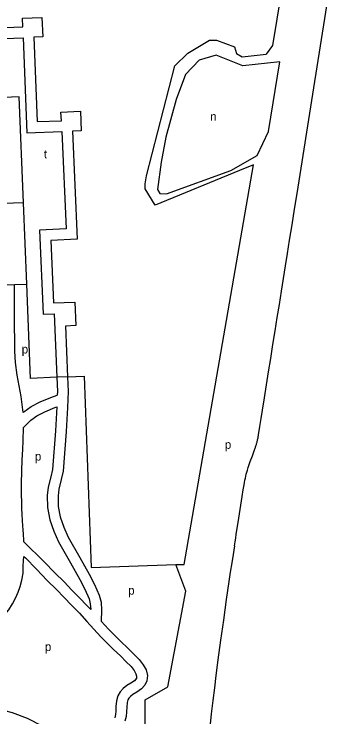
# Model space of a CAD drawing. Extents: x 158358 to 160383, y 379531 to 380764.
# Drawn here: x 160127.9 to 160276, y 379779.7 to 380106.3 of the extents above; entities that cross this region are included whole.
import ezdxf

# ---------------------------------------------------------------- set-up
doc = ezdxf.new("R2010")
doc.units = 0
for name, color, linetype in [('BLT_Basislijn', 7, 'Continuous'), ('BLT_Centroide', 7, 'Continuous'), ('BLT_Vlakafsluiter', 7, 'Continuous')]:
    doc.layers.add(name, color=color, linetype=linetype)

msp = doc.modelspace()

# ---------------------------------------------------------------- linework, layer by layer
at = {"layer": 'BLT_Basislijn'}
for p, q in [((160267.15, 380072.02), (160276.04, 380127.72)), ((160123.03, 379980.48), (160128.03, 379980.66)), ((160128.03, 379980.66), (160133.74, 379980.87))]:
    msp.add_line(p, q, dxfattribs=at)
for points in [[(160273.02, 380260.23), (160275.56, 380259.4), (160247.94, 380091.73)], [(160131.93, 380100.35), (160131.75, 380104.39), (160140.8, 380104.78), (160141.19, 380095.73), (160137.12, 380095.56)], [(160057.38, 380090.08), (160057.1, 380097.61), (160131.93, 380100.35)], [(160137.12, 380095.56), (160138.56, 380056.34), (160149.85, 380056.75)], [(160062.37, 380090.22), (160062.28, 380092.8), (160132.13, 380095.36), (160133.74, 380051.16), (160150.07, 380051.76), (160152.03, 380006.5), (160139.74, 380005.97), (160141.44, 379966.87), (160146.5, 379967.09), (160147.78, 379937.54)], [(160232.68, 380033.58), (160193.4, 380017.54), (160188.82, 380025.11), (160188.85, 380027.46), (160189.4, 380031.21), (160202.52, 380082.29), (160208.59, 380088.18), (160218.69, 380094.16), (160221.96, 380094.16), (160230.35, 380091.15), (160231.21, 380088.08), (160233.92, 380086.4), (160245.05, 380087.77)], [(160132.24, 380018.58), (160130.27, 380067.86), (160115.88, 380067.29), (160114.9, 380091.78), (160062.37, 380090.22)], [(160247.94, 380091.73), (160245.05, 380087.77)], [(160251.38, 380084.09), (160234.24, 380082.31), (160221.71, 380087.21), (160213.85, 380084.97), (160207.47, 380078.19), (160203.18, 380066.58), (160198.36, 380049.08), (160196.22, 380037.47), (160194.48, 380024.75), (160195.64, 380022.96), (160198.67, 380022.78), (160228.67, 380033.7), (160240.83, 380040.67), (160246.02, 380051.71), (160251.38, 380084.09)], [(160259.34, 380022.99), (160267.15, 380072.02)], [(160149.85, 380056.75), (160149.68, 380060.79), (160158.73, 380061.18), (160159.12, 380052.13), (160155.06, 380051.96)], [(160155.06, 380051.96), (160157.24, 380001.73), (160144.95, 380001.19), (160146.21, 379972.08)], [(160203.1, 379850.58), (160206.94, 379850.5), (160239.2, 380036.24), (160232.68, 380033.58)], [(160241.51, 379910.86), (160242.11, 379914.66), (160242.72, 379918.47), (160243.32, 379922.27), (160244.23, 379927.95), (160245.2, 379934.01), (160246.16, 379940.06), (160247.16, 379946.34), (160248.17, 379952.74), (160249.18, 379959.13), (160250.17, 379965.36), (160251.15, 379971.44), (160252.13, 379977.52), (160253.08, 379983.51), (160254.01, 379989.33), (160254.93, 379995.15), (160255.89, 380001.21), (160257.04, 380008.47), (160258.19, 380015.73), (160259.34, 380022.99)], [(160132.24, 380018.58), (160122.99, 380018.24)], [(160133.74, 379980.87), (160132.24, 380018.58)], [(160132.1, 379921.15), (160131.17, 379928.71), (160129.28, 379938.53), (160128.53, 379944.36), (160128.21, 379949.75), (160128.11, 379966.3), (160128.03, 379980.66)], [(160147.78, 379937.54), (160135.49, 379937.05), (160133.74, 379980.87)], [(160146.21, 379972.08), (160156.11, 379972.51), (160156.58, 379961.6), (160151.75, 379961.39)], [(160151.75, 379961.39), (160152.77, 379937.74)], [(160147.78, 379937.54), (160148.06, 379930.96)], [(160152.77, 379937.74), (160160.43, 379938.05), (160163.63, 379849.1), (160203.1, 379850.58)], [(160152.77, 379937.74), (160153.07, 379930.94)], [(160132.1, 379921.15), (160132.39, 379921.45), (160135.84, 379923.95), (160140.06, 379926.1), (160145.03, 379928.23), (160147.97, 379929.26)], [(160148.06, 379930.96), (160147.97, 379929.26)], [(160153.07, 379930.94), (160152.68, 379923.52), (160152.11, 379912.39), (160150.75, 379893.88), (160149.76, 379890.04), (160148.61, 379885.59), (160148.29, 379882.45), (160148.41, 379877.49), (160149.27, 379872.65), (160150.95, 379867.95), (160153.05, 379863.3), (160158.38, 379853.83), (160162.75, 379846.05), (160165.3, 379841.27), (160167.49, 379836.3), (160168.27, 379833.09), (160168.54, 379829.31), (160168.27, 379824.17)], [(160132.33, 379914.24), (160135.67, 379917.65), (160138.46, 379919.67), (160142.19, 379921.57), (160146.85, 379923.57), (160147.69, 379923.87)], [(160147.69, 379923.87), (160147.12, 379912.7), (160145.8, 379894.7), (160144.92, 379891.29), (160143.68, 379886.48), (160143.28, 379882.64), (160143.42, 379876.99), (160144.42, 379871.37), (160146.31, 379866.07), (160148.59, 379861.04), (160154.02, 379851.38), (160158.37, 379843.65), (160160.8, 379839.09), (160162.73, 379834.68), (160163.31, 379832.32), (160163.51, 379829.6)], [(160132.48, 379861.05), (160132.42, 379861.8), (160132.31, 379864.65), (160132.15, 379866.68), (160131.97, 379868.56), (160131.86, 379871.05), (160131.66, 379873.74), (160131.55, 379876.74), (160131.42, 379879.75), (160131.4, 379882.91), (160131.31, 379887.99), (160131.49, 379894.17), (160131.67, 379899.13), (160131.93, 379904.03), (160132.11, 379908.11), (160132.33, 379914.24)], [(160239.61, 379903.85), (160239.74, 379904.21), (160239.87, 379904.57), (160240, 379904.93), (160240.12, 379905.29), (160240.24, 379905.66), (160240.36, 379906.02), (160240.47, 379906.39), (160240.58, 379906.75), (160240.68, 379907.12), (160240.78, 379907.49), (160240.88, 379907.86), (160240.97, 379908.23), (160241.06, 379908.61), (160241.14, 379908.98), (160241.22, 379909.35), (160241.3, 379909.73), (160241.37, 379910.1), (160241.44, 379910.48), (160241.51, 379910.86)], [(160230.27, 379859.27), (160230.55, 379861.07), (160230.84, 379862.86), (160231.12, 379864.66), (160231.97, 379870.01), (160232.94, 379876.07), (160233.9, 379882.13), (160234.4, 379885.24), (160234.66, 379886.88), (160234.92, 379888.51), (160235.14, 379889.8), (160235.34, 379890.73), (160235.53, 379891.66), (160235.74, 379892.59), (160236, 379893.5), (160236.27, 379894.41), (160236.65, 379895.63), (160237.64, 379898.37), (160238.62, 379901.11), (160239.61, 379903.85)], [(160132.48, 379861.05), (160141.92, 379851.85), (160146.8, 379846.7), (160151.17, 379842.46), (160154.76, 379838.64), (160158.13, 379835.23), (160161.88, 379831.44), (160163.51, 379829.6)], [(160230.27, 379859.27), (160229.63, 379855.29), (160229, 379851.31), (160228.36, 379847.04), (160227.71, 379842.73), (160226.5, 379834.32), (160225.11, 379824.73), (160223.84, 379815.44), (160222.61, 379806.31), (160221.67, 379799.05), (160220.96, 379793.3), (160220.24, 379787.34), (160219.52, 379781.12), (160218.8, 379774.86), (160218.09, 379768.52), (160217.53, 379763.46), (160217.48, 379762.88), (160217.44, 379762.35)], [(160091.55, 379784.54), (160092.08, 379786.28), (160093.67, 379790.98), (160095.8, 379795.61), (160098.58, 379800.32), (160101.11, 379803.92), (160104.79, 379808.48), (160107.17, 379811.38), (160109.98, 379814.27), (160112.77, 379817.29), (160116.53, 379820.65), (160119.53, 379823.39), (160122.86, 379826.48), (160125.49, 379829.55), (160127.16, 379832.27), (160128.53, 379834.95), (160129.71, 379837.7), (160130.68, 379840.34), (160131.48, 379843.25), (160132.06, 379846.59), (160132.18, 379849.68), (160132.29, 379852.47), (160132.44, 379854.28)], [(160132.44, 379854.28), (160133.13, 379853.67), (160138.32, 379848.38), (160143.24, 379843.18), (160147.61, 379838.95), (160151.16, 379835.17), (160154.57, 379831.72), (160158.23, 379828.02), (160161.66, 379824.15), (160164.89, 379820.46), (160168.21, 379816.97), (160171.35, 379813.82), (160173.88, 379811.3), (160177.45, 379807.95), (160179.87, 379805.57), (160182.21, 379803.19), (160183.73, 379801.24), (160184.5, 379799.83), (160184.77, 379798.69), (160184.69, 379797.78), (160184.46, 379797.27), (160183.77, 379796.54), (160182.2, 379795.4), (160180.25, 379794.3), (160178.59, 379792.96), (160177.13, 379791.46), (160176.03, 379789.53), (160175.49, 379787.24), (160175.22, 379784.56), (160175.15, 379782.37), (160175, 379780.8), (160174.64, 379779.38)], [(160188.96, 379761.77), (160188.75, 379787.67), (160199.37, 379793.73), (160207.65, 379838.22), (160203.1, 379850.58)], [(160168.27, 379824.17), (160171.79, 379820.46), (160174.89, 379817.36), (160177.36, 379814.89), (160180.92, 379811.55), (160183.41, 379809.11), (160185.97, 379806.49), (160187.93, 379803.99), (160189.21, 379801.65), (160189.83, 379799.05), (160189.6, 379796.48), (160188.67, 379794.44), (160187.09, 379792.77), (160184.91, 379791.19), (160183.07, 379790.15), (160181.96, 379789.25), (160181.15, 379788.43), (160180.73, 379787.69), (160180.43, 379786.41), (160180.21, 379784.23), (160180.14, 379782.05), (160179.94, 379779.96), (160179.4, 379777.77)], [(160158.32, 379765.7), (160154.65, 379767.66), (160147.55, 379771.74), (160141.03, 379775.48), (160134.12, 379779), (160127.13, 379781.64), (160119.83, 379783.53), (160113.49, 379784.5), (160108.69, 379784.83), (160102.78, 379784.79), (160091.55, 379784.54)]]:
    msp.add_lwpolyline(points, dxfattribs=at)
at = {"layer": 'BLT_Vlakafsluiter'}
msp.add_line((160152.77, 379937.74), (160147.78, 379937.54), dxfattribs=at)

# ---------------------------------------------------------------- texts
at = {"layer": 'BLT_Centroide'}
for s, p in [('n', (160218.99, 380056.74)), ('t', (160141.75, 380039.3)), ('p', (160131.43, 379948.64)), ('p', (160225.83, 379904.32)), ('p', (160137.55, 379898.86)), ('p', (160180.89, 379836.56)), ('p', (160142.18, 379810.38))]:
    msp.add_text(s, height=4, dxfattribs=at).set_placement(p)

doc.saveas('drawing.dxf')
